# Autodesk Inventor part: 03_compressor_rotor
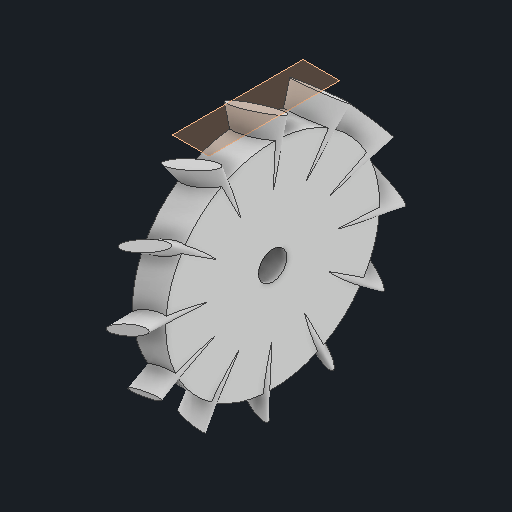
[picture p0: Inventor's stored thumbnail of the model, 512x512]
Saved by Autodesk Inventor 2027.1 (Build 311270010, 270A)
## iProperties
Created: 2026-10
Part Number: 03_compressor_rotor
Material: Generic
Document SubType Name: Modeling
Designer: BHAVAN KUMAR
Density: 1 g/cm^3
Appearance: Default
Author: BHAVAN KUMAR
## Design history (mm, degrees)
sketch "Sketch1"
  geometry: C1 r 45 at (0, 0); C2 r 6 at (0, 0); 1 further point
  constraints: 2 centre point, 2 coincident
  dimensions: "d0" = 90 diameter of C1; "d1" = 12 diameter of C2
extrude "Hub" new body sketch "Sketch1" distance "d2" = 14; taper "d3" = 0 deg
workplane "Work Plane1"
sketch "Sketch2" dims "d5" = 3, "d6" = 7
  geometry: 2 further points; 1 other entity
  constraints: 2 other
  dimensions: "d7" = 7 distance of point (0, 0) point (-7, 0)
workplane "Work Plane2"
sketch "Sketch3"
  geometry: C1 r 9.063 at (-7, 0); 1 further point
  constraints: 1 centre point
  dimensions: "d9" = 2 dimension on C1; "d10" = 10 dimension on C1; "d11" = 7 distance of point (0, 0) C1.centre
feature "Blade_Loft" sketch "Sketch3" dims "d12" = 0, "d13" = 90 deg, "d14" = 0, "d15" = 90 deg
pattern_circular "Blade_Pattern" dims angle "d17" = 360 deg
body "Solid1"
other parameters: "hub_bore" = 12 [user parameter], "hub_len" = 14 [user parameter], "blade_twist" = 25 deg [user parameter], "tip_radius" = 54 [user parameter], "root_len" = 14 [user parameter], "root_thick" = 3 [user parameter], "tip_thick" = 2 [user parameter], "d4" = 25, "d8" = 54
